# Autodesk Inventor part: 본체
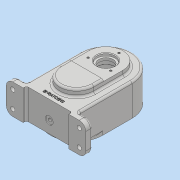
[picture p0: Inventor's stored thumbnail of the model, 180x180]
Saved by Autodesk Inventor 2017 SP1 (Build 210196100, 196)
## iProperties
Part Number: 본체
Material: 일반
Document SubType Name: Modeling
Designer: MRC
Density: 1 g/cm^3
Appearance: 기본값
Mass: 280.28 g
Surface Area: 581.797 cm^2
Volume: 280.28 cm^3
Author: MRC
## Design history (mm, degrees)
sketch "스케치14"
  geometry: L1 (0, 0)-(0, -45); L2 (-40, 0)-(-40, -45); L3 (40, -45)-(40, 0); L4 (0, 0)-(45, 0); L5 (40, -45)-(40, -82); L6 (40, -82)-(61, -82); L7 (61, -82)-(61, -92); L8 (61, -92)-(-61, -92); L9 (-61, -92)-(-61, -82); L10 (-61, -82)-(-40, -82); L11 (-40, -82)-(-40, -45); A1 r 40 centre (0, 0) between (40, 0) and (-40, 0); A2 r 40 centre (0, -45) between (-40, -45) and (40, -45); 1 further point
  constraints: 24 end point, 5 tangent, 4 perpendicular, 4 point on circle, 2 centre point, 2 equal length, 2 point on line, 2 vertical, 1 collinear, 1 horizontal, 1 midpoint, 1 parallel
  dimensions: "d58" = 45 distance of L1.start L1.end; "d59" = 90 deg angle of L1 L4 (derived); "d60" = 80 diameter of A2; "d61" = 47 distance from line of L8 L1.end; "d62" = 122 distance of L7.end L8.end; "d63" = 10 distance of L6.end L7.end
extrude "돌출11" new body sketch "스케치14" distance "d64" = 46; taper "d65" = 0 deg
sketch "스케치15"
  geometry: L1 (0, 0)-(0, -45); L2 (-40, 0)-(-40, -45); L3 (40, -45)-(40, 0); A1 r 40 centre (0, 0) between (40, 0) and (-40, 0) reference; A2 r 40 centre (0, 0) between (40, 0) and (-40, 0); A3 r 40 centre (0, -45) between (-40, -45) and (40, -45); 1 further point
  constraints: 8 end point, 4 point on circle, 4 tangent, 2 centre point, 1 midpoint, 1 parallel, 1 vertical
  dimensions: "d66" = 45 distance of L1.start L1.end; "d67" = 40 radius of A3
extrude "돌출12" join sketch "스케치15" distance "d68" = 3; taper "d69" = 0 deg
sketch "스케치16"
  geometry: L1 (0, 0)-(0, -45); L2 (-30, 0)-(-30, -45); L3 (30, -45)-(30, 0); A1 r 40 centre (0, -45) between (-40, -45) and (40, -45) reference; A2 r 40 centre (0, 0) between (40, 0) and (-40, 0) reference; A3 r 30 centre (0, 0) between (30, 0) and (-30, 0); A4 r 30 centre (0, -45) between (-30, -45) and (30, -45); 1 further point
  constraints: 8 end point, 4 point on circle, 4 tangent, 2 centre point, 1 midpoint, 1 parallel, 1 vertical
  dimensions: "d70" = 30 radius of A3
extrude "돌출13" cut sketch "스케치16" distance "d71" = 41; taper "d72" = 0 deg
sketch "스케치17"
  geometry: L1 (0, 0)-(0, -45); L2 (-26, 0)-(-26, -45); L3 (26, -45)-(26, 0); A1 r 40 centre (0, 0) between (40, 0) and (-40, 0) reference; A2 r 26 centre (0, 0) between (26, 0) and (-26, 0); A3 r 26 centre (0, -45) between (-26, -45) and (26, -45); 1 further point
  constraints: 8 end point, 4 point on circle, 4 tangent, 2 centre point, 1 midpoint, 1 parallel, 1 vertical
  dimensions: "d73" = 45 distance of L1.start L1.end; "d74" = 52 diameter of A3
extrude "돌출14" join sketch "스케치17" distance "d75" = 11; taper "d76" = 0 deg
sketch "스케치18"
  geometry: L1 (-26, 0)-(-26, -45) reference; L2 (26, -45)-(26, 0) reference; L3 (-26, -30)-(26, -30); A1 r 26 centre (0, 0) between (26, 0) and (-26, 0) reference
  constraints: 2 end point, 2 point on line, 1 perpendicular
  dimensions: "d77" = 30 distance from line of A1.centre L3
extrude "돌출15" cut sketch "스케치18" distance "d78" = 3; taper "d79" = 0 deg
hole "구멍1" diameter "d82" = 22; stored, may be unused: countersink angle "d86" = 90 deg, drill point angle "d88" = 118 deg; dims "d80" = 10, "d81" = 10, "d83" = 6, "d84" = 28, "d85" = 8, "d87" = 8
hole "구멍2" diameter "d91" = 20; stored, may be unused: countersink angle "d95" = 90 deg, drill point angle "d97" = 0 deg; dims "d89" = 10, "d90" = 10, "d92" = 6, "d93" = 28, "d94" = 8, "d96" = 12
sketch "스케치19"
  geometry: C1 r 11 at (0, 0) reference; C2 r 14 at (0, 0); A1 r 26 centre (0, 0) between (26, 0) and (-26, 0) reference
  constraints: 1 centre point, 1 coincident
  dimensions: "d98" = 28 diameter of C2
extrude "돌출16" cut sketch "스케치19" distance "d99" = 4; taper "d100" = 0 deg
chamfer "모따기4" distance "d101" = 1; stored, may be unused: second distance "d102" = 2, angle "d103" = 45 deg
fillet "모깎기5" dims "d104" = 0.3
fillet "모깎기6" dims "d105" = 3
sketch "스케치20"
  geometry: A1 r 30 centre (0, 0) between (30, 0) and (-30, 0) reference; 1 further point
  constraints: 1 vertical alignment
  dimensions: "d106" = 35 distance of A1.centre point (0, 35)
sketch "스케치21"
  geometry: A1 r 30 centre (0, -45) between (-30, -45) and (30, -45) reference; 1 further point
  constraints: 1 vertical alignment
  dimensions: "d107" = 35 distance of A1.centre point (0, -80)
hole "구멍3" sketch "스케치20" diameter "d108" = 3.242; stored, may be unused: countersink angle "d112" = 90 deg, drill point angle "d114" = 118 deg; dims "d109" = 8, "d110" = 28, "d111" = 8, "d113" = 10
hole "구멍4" sketch "스케치21" diameter "d115" = 3.242; stored, may be unused: countersink angle "d119" = 90 deg, drill point angle "d121" = 118 deg; dims "d116" = 8, "d117" = 28, "d118" = 8, "d120" = 10
fillet "모깎기7" dims "d131" = 10
sketch "스케치22"
  geometry: A1 r 10 centre (-11, 10) between (-21, 10) and (-11, 0) reference; A2 r 10 centre (-11, 36) between (-11, 46) and (-21, 36) reference; 3 further points
  constraints: 2 coincident
hole "구멍5" sketch "스케치22" at (-11, 36), (-11, 10) diameter "d132" = 6.6; stored, may be unused: countersink angle "d136" = 90 deg, drill point angle "d138" = 118 deg; dims "d133" = 8, "d134" = 11, "d135" = 2, "d137" = 10
sketch "스케치23"
  geometry: A1 r 26 centre (0, 0) between (26, 0) and (-26, 0) reference; 1 further point
  constraints: 1 vertical alignment
  dimensions: "d139" = 20 distance of A1.centre point (0, 20)
hole "구멍6" sketch "스케치23" at (0, 20) diameter "d140" = 3.242; stored, may be unused: countersink angle "d144" = 90 deg, drill point angle "d146" = 118 deg; dims "d141" = 8, "d142" = 11, "d143" = 2, "d145" = 10
fillet "모깎기8" dims "d150" = 3
sketch "스케치24"
  geometry: L1 (-51, -92)-(51, -92) reference; L2 (-35, -87)-(35, -87); L3 (35, -87)-(35, -92); L4 (35, -92)-(-35, -92); L5 (-35, -92)-(-35, -87); 2 further points
  constraints: 8 end point, 2 midpoint, 2 parallel, 1 horizontal, 1 perpendicular
  dimensions: "d151" = 70 distance of L3.end L4.end; "d152" = 5 distance of L2.end L3.end
extrude "돌출17" cut sketch "스케치24" stored distance "d153" = 4; taper "d154" = 0 deg
fillet "모깎기9" dims "d155" = 3
fillet "모깎기10" dims "d156" = 5
node "작업 평면1"
sketch "스케치25"
  geometry: L1 (-40, -49)-(40, -49) reference; C1 r 6 at (0, -28); 1 further point
  constraints: 1 centre point, 1 vertical alignment
  dimensions: "d158" = 12 diameter of C1; "d159" = 21 distance from line of C1.centre L1
extrude "돌출18" join sketch "스케치25" stored distance "d160" = 4; taper "d161" = 0 deg
fillet "모깎기11" dims "d162" = 3
sketch "스케치26"
  geometry: L1 (0, 46)-(64, 46) reference; L2 (-8, -3)-(72, -3) reference; C1 r 6 at (32, 18); 2 further points
  constraints: 1 centre point, 1 midpoint, 1 vertical alignment
  dimensions: "d172" = 12 diameter of C1; "d173" = 21 distance from line of C1.centre L2
extrude "돌출19" cut sketch "스케치26" distance "d174" = 1; taper "d175" = 0 deg
hole "구멍8" diameter "d178" = 4.917; stored, may be unused: countersink angle "d182" = 90 deg, drill point angle "d184" = 118 deg; dims "d176" = 10, "d177" = 10, "d179" = 12, "d180" = 11, "d181" = 2, "d183" = 17.1
sketch "스케치27"
  geometry: L1 (-32, -87)-(32, -87) reference; L2 (-51, -92)-(-61, -92) reference; 2 further points
  constraints: 1 midpoint, 1 vertical alignment, 1 other
  dimensions: "d186" = 12 distance from line of point (0, -80) L2
feature "엠보싱1" sketch "스케치27" dims "d66" = 45, "d67" = 40, "d187" = 0.5, "d188" = 0
sketch "스케치28"
  geometry: A1 r 6 centre (0, 28) between (0, 34) and (0, 22) reference; 1 further point
hole "구멍9" sketch "스케치28" at (0, 28) diameter "d189" = 4.917; stored, may be unused: countersink angle "d193" = 90 deg, drill point angle "d195" = 118 deg; dims "d190" = 12, "d191" = 11, "d192" = 2, "d194" = 25.6
node "솔리드2"
pattern_circular "원형 패턴2" dims angle "d126" = 180 deg
pattern_circular "원형 패턴3" dims angle "d129" = 180 deg
mirror "미러1"
pattern_circular "원형 패턴4" dims angle "d148" = 360 deg
other parameters: "d157" = 43
